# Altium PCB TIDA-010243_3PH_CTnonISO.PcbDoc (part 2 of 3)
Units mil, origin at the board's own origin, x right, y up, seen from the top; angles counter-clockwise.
Board outline 6131.89 x 7490.17 mil, 2 copper layers (Top Layer, Bottom Layer), stack 62 mil thick; 208 components, 218 nets, 747 pads, 147 vias.
Unrouted connection lines stored in the file: 258.
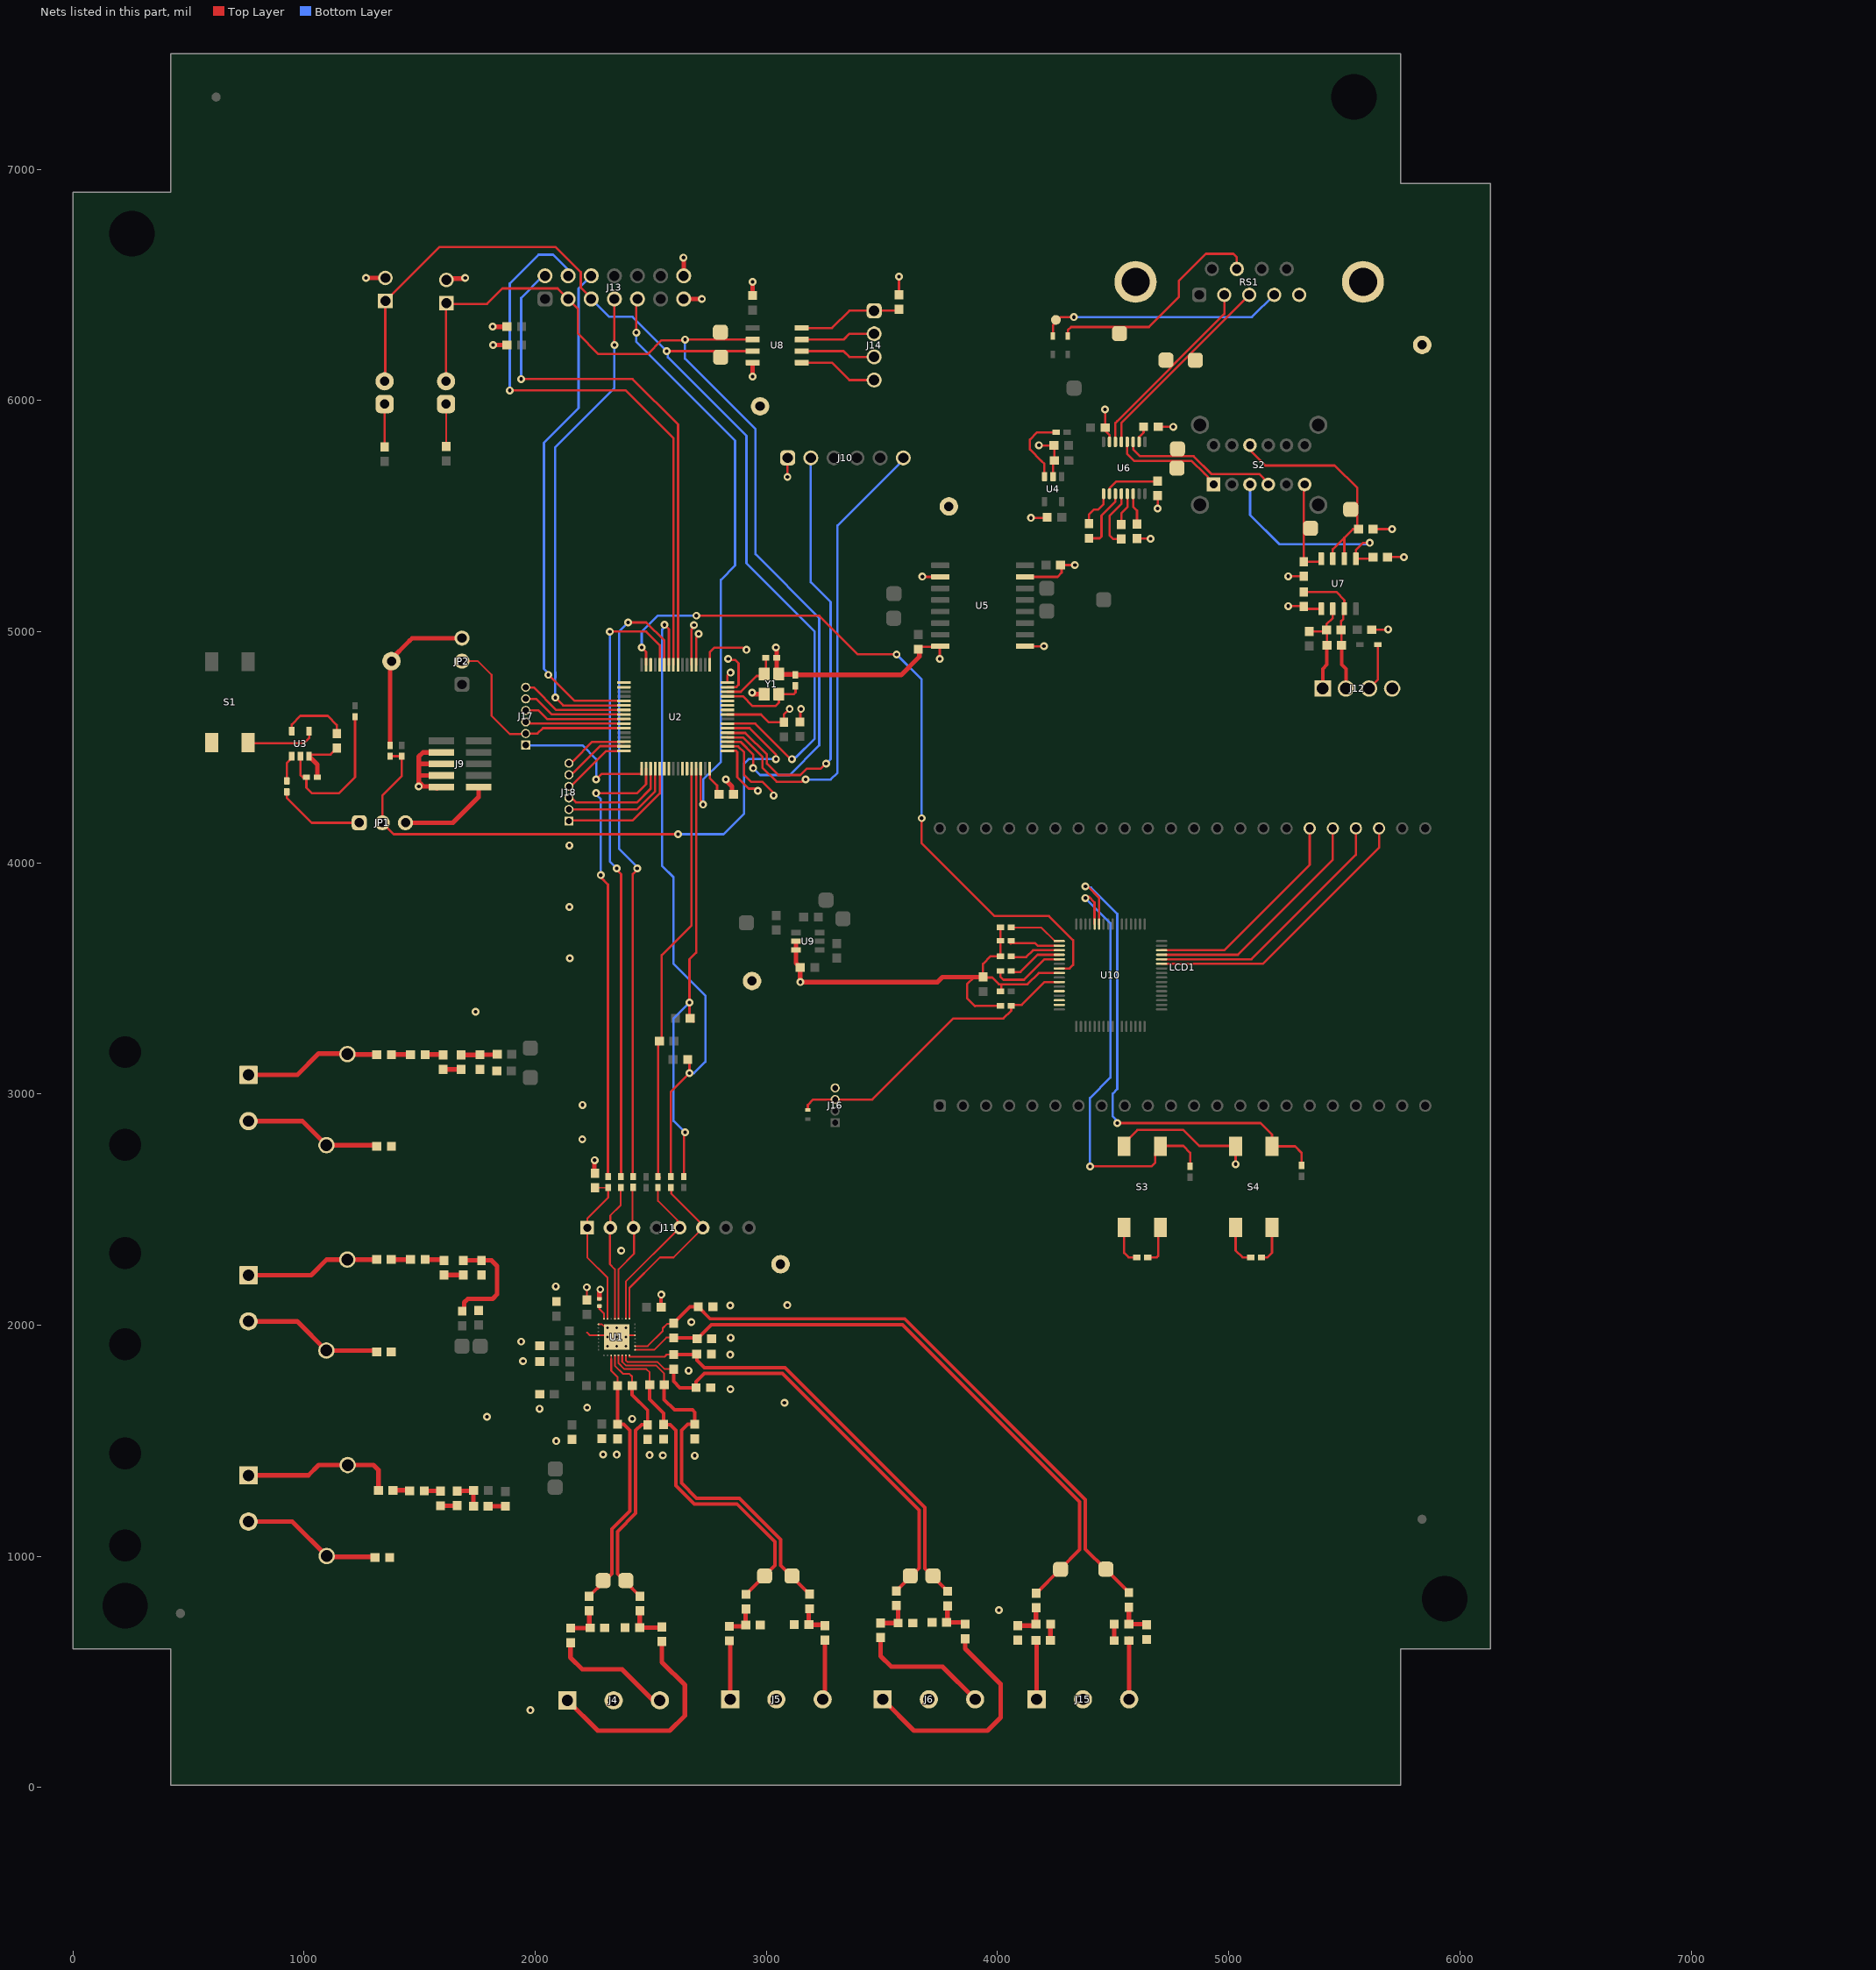
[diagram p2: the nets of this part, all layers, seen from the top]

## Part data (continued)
LBL1: library part CMP-0003625-1, "Thermal Transfer Printable Labels, 0.650\" W x 0.200\" H - 10,000 per roll", Manufacturer=Brady, Supplier Part Number 1=97C5133
LCD1: library part CMP-0079272-1, "160 Segment LCD Display, TH", Manufacturer="Adkom Elektronik"
Logo2: library part CMP-0074844-1
Logo3: library part CMP-0074847-1, "FCC_disclaimer"
logo4: library part CMP-0074835-1, "IEC 61010-1 High Voltage Warning"
Logo4: library part CMP-0074769-1
logo5: library part CMP-0074837-2, "IEC 61010-1 Hot Surface Warning", Manufacturer="Texas Instruments"
R1 R9 R10 R21 R24 R34 R35 R39 R41 R45 R47 R51 R56 R64 R112 R114: library part CMP-0025874-4, "RES, 0, 5%, 0.1 W, AEC-Q200 Grade 0, 0603", Manufacturer=Panasonic, Power_W=100mW, Supplier Part Number 1=P0.0GCT-ND, TempCo="600 ppm/C", Tolerance_%=5%, Value2=0.1W, Value_Code=0000, ValueDisplayed=0
R2 R3 R4 R11 R12 R13 R25 R26 R27: library part CMP-0023521-3, "RES, 330 k, 0.1%, 0.1 W, 0603", Manufacturer="Susumu Co Ltd", Power_W=100mW, Supplier Part Number 1=RG16P330KBCT-ND, TempCo="25 ppm/C", Tolerance_%=0.1%, Value2=0.1W, Value_Code=330k
R5 R8 R14 R19 R28 R33: library part CMP-0084355-1, "RES, 1.00 k, 0.5%, 0.1 W, 0603", Manufacturer=Yageo, Power_W=100mW, TempCo="25 ppm/C", Tolerance_%=0.5%, Value2=0.1W, Value_Code=1k00, ValueDisplayed=1.00k
R6 R16 R31: library part CMP-0001856-2, "Varistor 275 VAC, 100 A, TH", Manufacturer=TDK, Supplier Part Number 1=96K7679
R7 R17 R32: library part CMP-0025554-3, "RES, 750, 0.5%, 0.1 W, 0603", Manufacturer="Yageo America", Power_W=100mW, TempCo="50 ppm/C", Tolerance_%=0.5%, Value2=0.1W, Value_Code=750R, ValueDisplayed=750
R15: library part CMP-0026908-3, "RES, 33, 5%, 0.063 W, AEC-Q200 Grade 0, 0402", Manufacturer=Vishay-Dale, Power_W=63mW, Supplier Part Number 1=541-33JCT-ND, TempCo="200 ppm/C", Tolerance_%=5%, Value2=0.063W, Value_Code=33R0, ValueDisplayed=33
R18 R20 R22 R23 R30: library part CMP-0026908-2, "RES, 33, 5%, 0.063 W, 0402", Manufacturer=Vishay-Dale, Power_W=63mW, Supplier Part Number 1=541-33JCT-ND, TempCo="200 ppm/C", Tolerance_%=5%, Value2=0.063W, Value_Code=33R0, ValueDisplayed=33
R29: library part CMP-0026822-3, "RES, 0, 5%, 0.063 W, AEC-Q200 Grade 0, 0402", Manufacturer=Vishay-Dale, Power_W=63mW, Supplier Part Number 1=541-0.0JCT-ND, TempCo="200 ppm/C", Tolerance_%=5%, Value2=0.063W, Value_Code=0000, ValueDisplayed=0
R36 R40 R42 R46 R48 R52 R109 R110 R111 R113 R115: library part CMP-0025080-3, "RES, 2.00 k, 0.5%, 0.1 W, 0603", Manufacturer="Yageo America", Power_W=100mW, TempCo="25 ppm/C", Tolerance_%=0.5%, Value2=0.1W, Value_Code=2k00, ValueDisplayed=2.00k
R37 R38 R43 R44 R49 R50 R57 R63: library part CMP-0022575-4, "RES, 6.49, 1%, 0.1 W, AEC-Q200 Grade 0, 0603", Manufacturer=Vishay-Dale, Power_W=100mW, Supplier Part Number 1=541-6.49HHCT-ND, TempCo="100 ppm/C", Tolerance_%=1%, Value2=0.1W, Value_Code=6R49, ValueDisplayed=6.49
R53 R54: library part CMP-0022736-2, "RES, 100, 1%, 0.1 W, 0603", Manufacturer="Yageo America", Power_W=100mW, Supplier Part Number 1=311-100HRCT-ND, TempCo="200 ppm/C", Tolerance_%=1%, Value2=0.1W, Value_Code=100R, ValueDisplayed=100
R55 R65: library part CMP-0026935-3, "RES, 47 k, 5%, 0.063 W, AEC-Q200 Grade 0, 0402", Manufacturer=Vishay-Dale, Power_W=63mW, Supplier Part Number 1=541-47KJCT-ND, TempCo="200 ppm/C", Tolerance_%=5%, Value2=0.063W, Value_Code=47k0, ValueDisplayed=47k
R58: library part CMP-0021998-2, "RES, 10.0 k, 1%, 0.1 W, 0603", Manufacturer=Vishay-Dale, Power_W=100mW, Supplier Part Number 1=541-10.0KHCT-ND, TempCo="100 ppm/C", Tolerance_%=1%, Value2=0.1W, Value_Code=10k0, ValueDisplayed=10.0k
R59 R61: library part CMP-0021990-4, "RES, 100 k, 1%, 0.1 W, AEC-Q200 Grade 0, 0603", Manufacturer=Vishay-Dale, Power_W=100mW, Supplier Part Number 1=541-100KHCT-ND, TempCo="100 ppm/C", Tolerance_%=1%, Value2=0.1W, Value_Code=100k
R60 R62: library part CMP-0094948-1, "0 Ohms Jumper 0.1W, 1/10W Chip Resistor 0402 (1005 Metric) - Thick Film", Digikey Part Number=2679-CR0402-10W-000TTR-ND, Manufacturer=Venkel, Operating Temperature Range="-55°C to +155°C", Power_W=100mW
R66 R67: library part CMP-0025950-3, "RES, 100 k, 1%, 0.063 W, AEC-Q200 Grade 0, 0402", Manufacturer=Vishay-Dale, Power_W=63mW, Supplier Part Number 1=541-100KLCT-ND, TempCo="100 ppm/C", Tolerance_%=1%, Value2=0.063W, Value_Code=100k
R101: library part CMP-0027004-2, "RES, 0, 5%, 0.063 W, 0402", Manufacturer="Yageo America", Power_W=63mW, Supplier Part Number 1=311-0.0JRCT-ND, TempCo="200 ppm/C", Tolerance_%=5%, Value2=0.063W, Value_Code=0000, ValueDisplayed=0
R102 R105 R106: library part CMP-0025817-4, "RES, 4.7 k, 5%, 0.1 W, AEC-Q200 Grade 0, 0603", Manufacturer=Vishay-Dale, Power_W=100mW, Supplier Part Number 1=541-4.7KGCT-ND, TempCo="200 ppm/C", Tolerance_%=5%, Value2=0.1W, Value_Code=4k70, ValueDisplayed=4.7k
R103 R108: library part CMP-0025698-4, "RES, 100 k, 5%, 0.1 W, AEC-Q200 Grade 0, 0603", Manufacturer=Vishay-Dale, Power_W=100mW, Supplier Part Number 1=541-100KGCT-ND, TempCo="200 ppm/C", Tolerance_%=5%, Value2=0.1W, Value_Code=100k
R107: library part CMP-0024624-2, "RES, 120, 0.5%, 0.1 W, 0603", Manufacturer="Yageo America", Power_W=100mW, TempCo="50 ppm/C", Tolerance_%=0.5%, Value2=0.1W, Value_Code=120R, ValueDisplayed=120
RS1: library part CMP-0079577-1, "Receptacle, D-SUB-9, 2.74mm, Gold, TH", Color=Black, Current_A=6A, Manufacturer="TE Connectivity", Supplier Part Number 1=A32036-ND, Voltage_V=125V
S1 S3 S4: library part CMP-0002197-2, "Switch, Tactile, SPST-NO, 12 V, SMD", CurrentRating_mA=50A, Manufacturer=APEM, Supplier Part Number 1=679-2461-1-ND
S2: library part CMP-0002195-2, "Switch, Slide, 4PDT,TH", CurrentRating_mA=300A, Manufacturer="TE Connectivity", Supplier Part Number 1=450-1592-ND
TP1 TP2 TP3 TP4 TP5 TP6: library part CMP-0055137-1, "Test Point, Miniature, Red, TH", Color=Red, Manufacturer=Keystone, Supplier Part Number 1=36-5000-ND
U1: library part CMP-0089590-1, "8-Channel, Simultaneously-Sampling, 24-Bit, Delta-Sigma ADC", Manufacturer="Texas Instruments", Max Supply Voltage=3.6V, Min Supply Voltage=1.65V, Operating Temperature Range="-40°C to +125°C"
U2: library part CMP-0093955-1, "Mixed-Signal Microcontrollers LQFP64 80MHz 128KB Flash and 32KB RAM 60 GPIO's 32bits ARM Cortex-M0+ 7 Timers", Frequency_Fixed=80MHz, Manufacturer="Texas Instruments", Max Supply Voltage=3.6V, Min Supply Voltage=1.62V, Operating Temperature Range="-40°C to +125°C"
U3: library part CMP-0084477-1, "Nano Power, Wide VIN Voltage Detector with Programmable Delay, DBV0005A (SOT-23-5)", Alternate Manufacturer="Texas Instruments"
U4: library part CMP-0073793-1, "150-mA, 30-V, Ultra-Low IQ, Wide Input Low-Dropout Regulator with Reverse Current Protection, DBV0005A (SOT-23-5)", Alternate Manufacturer="Texas Instruments", Alternate PartNumber=TPS70933DBVT
U5: library part CMP-0094636-1, Digikey Part Number=296-ISO6731DWRCT-ND, Manufacturer="Texas Instruments", Max Supply Voltage=5.5V, Min Supply Voltage=1.71V, Mouser Part Number=595-ISO6731DWR, Operating Temperature Range="-40°C to +125°C"
U6: library part CMP-0044123-1, "3-V to 5.5-V Multichannel RS-232 Line Driver / Receiver with ±15-kV IEC ESD Protection, 0 to 70 degC, 16-Pin TSSOP (PW), Green (RoHS & no Sb/Br)", Drivers Per Package=2, Supply Voltage(s)(V)="3.3 or 5.0"
U7: library part CMP-0089978-1, "500 kbps RS-485 Transceivers With ±8-kV IEC ESD Protection", Manufacturer="Texas Instruments", Max Supply Voltage=5.5V, Min Supply Voltage=4.5V, Nominal Supply Current=275-440uA, Operating Temperature Range="-40°C to +125°C"
U8: library part CMP-0095064-1, Digikey Part Number=296-ISO6720BDRCT-ND, Manufacturer="Texas Instruments", Max Supply Voltage=5.5V, Min Supply Voltage=1.71V, Mouser Part Number=595-ISO6720BDR, Operating Temperature Range="-40°C to +125°C"
U9: library part CMP-0092928-2, "3-Axis Linear Hall Effect Sensor With I2C Interface SOT23-6", Manufacturer="Texas Instruments", Max Supply Voltage=3.6V, Min Supply Voltage=1.7V, Operating Supply Current=2.3-2.7mA, Operating Temperature Range="-40°C to +125°C"
U10: library part CMP-0076610-2, "16 MHz Ultra-Low-Power Microcontroller with 16 KB FRAM, 2 KB SRAM, 60 IO, 10 ch ADC10, LCD, IR Logic, PM0064A (LQFP-64)", Alternate Manufacturer="Texas Instruments", Alternate PartNumber=MSP430FR4133IPM
Y1: library part CMP-0085525-1, "Crystal, 16.384 MHz, 50 ppm, 10 pF, SMD", Frequency Stability="30 ppm", Frequency Tolerance="50 ppm", Frequency_Fixed=16.384MHz, Load Capacitance="10 pF", Manufacturer=Epson

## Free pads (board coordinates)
  rrect50% 64.96x64.96 smd: 1(1978.35,3070.87) 1(2086.61,1377.95) 1(2293.31,895.67) 1(2391.73,895.67) 1(2800.83,6295.02) 1(2913.39,3740.16) 1(3110.24,915.35) 1(3257.87,3838.58) 1(3331.38,3758.29) 1(3551.63,5164.02) 1(4212.6,5088.58) 1(4330.71,6053.15) 1(4778.18,5790.08) 1(5527.49,5528.23) 2(1978.35,3198.82) 2(2086.05,1299.52) 2(2802.04,6187.02) 2(2992.13,915.35) 2(3550.51,5057.79) 2(4212.6,5187.01) 2(4527.56,6289.37) 2(4728.72,6174.24) 2(4776.02,5707) 2(5353.34,5446.73) 3(1683.07,1909.45) 3(3622.05,915.35) 3(4458.66,5137.8) 3(4855.23,6173.59) 4(1761.81,1909.45) 4(3720.47,915.35) 5(4468.5,944.88) 6(4272.26,943.9)
  round 42.13 smd: 1(4251.97,6348.43)

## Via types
v1: diameter 34, hole 16, Top Layer to Bottom Layer, 97 vias
v2: diameter 34, hole 16, Top Layer to Bottom Layer, tented both sides, 41 vias
v3: diameter 23.62, hole 11.81, Top Layer to Bottom Layer, 9 vias

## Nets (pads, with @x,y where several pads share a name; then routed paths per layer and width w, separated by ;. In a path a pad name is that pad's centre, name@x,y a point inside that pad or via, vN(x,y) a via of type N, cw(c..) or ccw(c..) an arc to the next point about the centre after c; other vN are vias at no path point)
232_DIN: pad.1@4778.18,5790.08 S2.4 U6.11 | length 683.2
  Top Layer w10: U6.11@4586.27,5820.73 4586.27,5787.99 4615.53,5758.72 4847.37,5758.72 4924.36,5681.73 5131.37,5681.73 5170.74,5642.36 S2.4@5170.74,5636.67
232_ROUT: pad.2@4776.02,5707 S2.1 U6.12 | length 484.5
  Top Layer w10: U6.12@4560.68,5820.73 4560.68,5768.4 4591.09,5737.98 4839.68,5737.98 4894.08,5683.58 4925.5,5652.16 4925.5,5645.69 S2.1@4934.52,5636.67
485_D: pad.2@5353.34,5446.73 R105.1 S2.6 U7.4 | length 408.9
  Top Layer w10: S2.6@5324.8,5629.92 5324.32,5629.44 R105.1@5324.32,5302.22 5387.25,5302.22 U7.4@5399.99,5314.97
485_R: C40.2 S2.3 U7.1 | length 905.5
  Top Layer w10: v1@5601.58,5392.51 v1(5610.24,5383.86) 5580.71,5383.86 5549.99,5353.14 U7.1@5549.99,5314.97 5616.18,5314.97 C40.2@5623.76,5322.55
  Bottom Layer w10: S2.3@5092,5636.67 5092,5504.59 5218.6,5377.99 5604.37,5377.99 v1(5610.24,5383.86)
485_RE_DE: pad.1@5527.49,5528.23 R106.1 S2.10 U7.2 U7.3 | length 1109.8
  Top Layer w10: S2.10@5092,5805.97 5092,5784.27 5157.76,5718.5 5458.32,5718.5 5555.99,5620.83 ; U7.3@5449.99,5314.97 5449.99,5356.28 5499.99,5406.28 ; U7.2@5499.99,5314.97 5499.99,5406.28 ; R106.1@5551.17,5433.68 5555.99,5438.5 R106.1@5555.99,5443.32 ; pad.1@5555.99,5528.23 5555.99,5620.83 ; 5499.99,5406.28 5537.03,5443.32 R106.1@5555.99,5443.32 ; R106.1@5555.99,5443.32 5555.99,5620.83
ACLK: U10.15
ACT: D1.2 J7.1 J13.3 pad.1@2800.83,6295.02 U2.35 U8.2 | length 4432.3
  Top Layer w10: D1.2@1614.17,6082.68 1614.17,6417.32 1791.34,6417.32 1858.29,6484.27 2096.87,6484.27 J13.3@2142.23,6438.92 2185.04,6396.11 2185.04,6289.37 2273.62,6200.79 2487.61,6200.79 2546.67,6259.84 v1@2647.64,6259.84 ; v1(2647.64,6263.18) U8.2@2940.24,6263.18 ; U2.35@2831.79,4523.4 2888.02,4523.4 2942.91,4468.5 v1(2942.91,4409.45)
  Bottom Layer w10: v1(2647.64,6263.18) 2647.64,6181.1 2952.76,5875.98 2952.76,5334.65 3228.35,5059.06 3228.35,4507.87 3100.39,4379.92 2972.44,4379.92 v1(2942.91,4409.45)
ACT_ISO: J14.2 U8.7 | length 323.6
  Top Layer w10: U8.7@3152.84,6263.18 3333.58,6263.18 3358.58,6288.18 J14.2@3466.1,6288.18
ADS_CS: R29.2 R59.1 U2.58 | length 2788.4
  Top Layer w10: v1@2568.9,5019.68 2577.86,5010.73 U2.58@2577.86,4856.08 ; R29.2@2586.46,2642.86 2586.46,3009.69 v2(2667.32,3090.55) 2667.32,3149.61 R59.1@2657.48,3159.45
  Bottom Layer w10: v1@2568.9,5029.53 2565.55,5029.53 2554.46,5018.44 2554.46,5015.09 2548.87,5009.5 2548.87,4183.42 2549.21,4183.07 2549.21,3986.22 2598.43,3937.01 2598.43,3562.99 2736.22,3425.2 2736.22,3139.76 2687.01,3090.55 v2(2667.32,3090.55)
  other v1: 2559.06,5029.53
ADS_DIN_MSP_DOUT: R18.2 U2.60 | length 2703.2
  Top Layer w10: v1(2322.83,5000) 2480.32,5000 2538.49,4941.83 U2.60@2538.49,4856.08 ; v1(2352.36,3976.38) 2352.36,3969.88 2371.22,3951.03 2371.22,2643.51 R18.2@2370.39,2642.68
  Bottom Layer w10: v1(2322.83,5000) 2322.83,4005.91 v1(2352.36,3976.38)
ADS_DOUT_MSP_DIN: R20.2 U2.59 | length 2747.8
  Top Layer w10: v1(2401.57,5039.37) 2480.31,5039.37 2558.17,4961.51 U2.59@2558.17,4856.08 ; R20.2@2423.15,2642.86 2422.25,2643.76 2422.25,3951.19 2440.94,3969.88 v1(2440.94,3976.38)
  Bottom Layer w10: v1(2401.57,5039.37) 2362.2,5000 2362.2,4061 2440.94,3982.26 v1(2440.94,3976.38)
ADS_DRDY: R23.2 R58.2 U2.28 | length 1833.2
  Top Layer w10: R23.2@2530.9,2642.86 2530.9,3208.79 2532.56,3210.45 2532.56,3214.65 2546.26,3228.35 R58.2@2547.24,3228.35 ; R23.2@2530.9,2646.26 R23.2@2539.37,2637.8 ; R58.2@2547.24,3232.28 2547.24,3600.39 2676.28,3729.43 U2.28@2676.28,4407.26
ADS_SYNC_RESET: R30.2 R61.1 U2.29 | length 1888.1
  Top Layer w10: R30.2@2642.94,2642.86 2642.94,2678.25 ; 2642.94,2705.54 2642.94,2816.79 2643.05,2816.89 2643.05,2830.05 v2(2647.64,2834.65) ; 2643.06,2679.98 2643.06,2703.72 ; R61.1@2667.32,3336.61 v2(2667.32,3395.67) 2667.32,3582.68 2695.97,3611.32 U2.29@2695.97,4407.26 ; R61.1@2680.12,3316.93 R61.1@2683.98,3313.07
  Bottom Layer w10: v2(2647.64,2834.65) 2598.43,2883.86 2598.43,3326.77 v2(2667.32,3395.67)
BTN1: R67.1 S4.4 U10.59 | length 2240.4
  Top Layer w10: v1(4379.92,3897.64) 4389.76,3897.64 4438.98,3848.42 U10.59@4438.98,3735.24 ; v1(4517.72,2874.02) 5137.8,2874.02 5187.01,2824.8 S4.4@5187.01,2773.62 5287.4,2773.62 5314.96,2746.06 R67.1@5314.96,2690.94 R67.1@5314.96,2687.01
  Bottom Layer w10: v1(4379.92,3897.64) 4384.51,3893.05 4404.2,3893.05 4517.72,3779.53 4517.72,3021.65 4498.03,3001.97 4498.03,2903.54 4510.01,2891.56 4510.01,2888.22 4517.72,2880.51 v1(4517.72,2874.02)
BTN2: R66.1 S3.4 U10.60 | length 1935.9
  Top Layer w10: v1@4394.06,3853.62 4419.29,3828.39 U10.60@4419.29,3735.24 ; v1(4399.61,2687.01) 4665.35,2687.01 4682.17,2703.82 4682.17,2743.19 4714.57,2775.59 4803.15,2775.59 4832.68,2746.06 R66.1@4832.68,2687.01
  Bottom Layer w10: v1@4379.92,3848.43 v1(4379.92,3847.76) 4488.19,3739.5 4488.19,3070.87 4399.61,2982.28 v1(4399.61,2687.01)
CLKIN_ADS_T: C45.1 J11.1 R15.1 U1.23 | length 695.1
  Top Layer w6: C45.1@2258.61,2594.04 2308.61,2594.04 R15.1@2306.69,2592.12 ; R15.1@2312.84,2598.27 R15.1@2312.99,2598.43
  Top Layer w8: U1.23@2312.99,2027.56 2312.99,2204.72 2224.8,2292.91 J11.1@2224.8,2421.26 2224.8,2461.02 2306.69,2542.91 2315.5,2551.72 R15.1@2315.5,2595.61
COM0: LCD1.28 U10.46 | length 937.4
  Top Layer w10: U10.46@4709.65,3622.05 4980.31,3622.05 5350,3991.73 5350,4129.53 LCD1.28@5354.33,4133.86
COM1: LCD1.27 U10.45 | length 1008.9
  Top Layer w10: U10.45@4729.25,3602.36 5039.37,3602.36 5450,4012.99 LCD1.27@5450,4131.1
COM2: LCD1.26 U10.44 | length 1142.4
  Top Layer w10: U10.44@4709.65,3582.68 5098.43,3582.68 5550,4034.25 LCD1.26@5550,4149.21
COM3: LCD1.25 U10.43 | length 1232.3
  Top Layer w10: U10.43@4709.65,3562.99 5147.64,3562.99 5650,4065.35 LCD1.25@5650,4149.21
CS_ADS_T: J11.6 R29.1 U1.17 | length 792.9
  Top Layer w8: U1.17@2407.48,2027.97 2407.48,2161.42 2539.37,2293.31 2598.43,2293.31 2724.8,2419.69 2724.8,2432.68 2588.58,2568.9 R29.1@2588.58,2598.43
CTS_FTDI: J10.2 U2.37 | length 1911.2
  Top Layer w10: U2.37@2831.79,4562.77 2832.7,4561.86 2859.92,4561.86 2908.61,4561.86 3001.97,4468.5 3001.97,4429.13 3051.18,4379.92 3146.73,4379.92 3173.96,4407.15 3234.6,4407.15 3256.58,4429.13 v1(3257.87,4429.13)
  Bottom Layer w10: J10.2@3191.88,5751.41 3191.88,5213.63 3277.56,5127.95 3277.56,4448.82 v1(3257.87,4429.13)
DIN_ADS_T: J11.2 R18.1 U1.21 | length 593.2
  Top Layer w8: J11.2@2322.83,2411.42 2322.83,2263.78 2344.49,2242.13 U1.21@2344.49,2027.56 ; J11.2@2322.83,2431.1 2324.8,2433.07 2324.8,2474.52 2369.97,2519.69 R18.1@2369.97,2601.1 ; J11.2@2323.18,2411.07 2324.8,2412.7 J11.2@2324.8,2421.26
DOUT_ADS_T: J11.3 R20.1 U1.20 | length 597.6
  Top Layer w8: U1.20@2360.24,2027.97 2360.24,2242.13 2427.17,2309.06 J11.3@2427.17,2421.26 ; R20.1@2421.26,2594.87 2421.26,2424.8 J11.3@2424.8,2421.26 ; R20.1@2423.24,2595.97 R20.1@2424.33,2594.87
DRDY_ADS_T: J11.5 R23.1 U1.18 | length 707
  Top Layer w8: U1.18@2391.73,2027.97 2391.73,2188.19 J11.5@2624.8,2421.26 2615.03,2431.03 2615.03,2453.86 2531.27,2537.63 2531.27,2592.35 2532.64,2590.98 2532.64,2593.87 R23.1@2530.9,2595.61
DVDD_ISO_Pulse: C44.1 J14.1 U8.8 | length 454.3
  Top Layer w10: U8.8@3152.84,6313.18 3283.58,6313.18 3358.58,6388.18 J14.1@3466.1,6388.18 3567.4,6388.18 C44.1@3573.51,6394.29
EM_RX_SECC_TX_UART: J13.4 U2.57 | length 2594.6
  Top Layer w10: v2(1889.76,6043.31) 2391.73,6043.31 2597.54,5837.5 U2.57@2597.54,4856.08
  Bottom Layer w10: v2(1889.76,6043.31) 1889.76,6505.91 2014.21,6630.36 2077.54,6630.36 2142.23,6565.67 J13.4@2142.23,6538.92
EM_SECC_GPIO_UART: J13.6 U2.5 | length 2191.4
  Top Layer w10: v1(2057.09,4812.99) 2169.51,4700.57 U2.5@2382.97,4700.57
  Bottom Layer w10: v1(2057.09,4812.99) 2057.09,4818.88 2037.4,4838.56 2037.4,5816.93 2187.58,5967.11 2187.58,6484.27 J13.6@2242.23,6538.92
EM_TX_SECC_RX_UART: J13.2 U2.56 | length 2294.1
  Top Layer w10: v2(1938.98,6092.52) 2421.26,6092.52 2618.04,5895.74 2618.04,4856.89 U2.56@2617.23,4856.08
  Bottom Layer w10: v2(1938.98,6092.52) 1938.98,6443.19 2034.71,6538.92 J13.2@2042.23,6538.92
GND: C1.2 C3.1 C4.2 C5.2 C6.2 C7.2 C9.1 C10.2 C12.1 C13.2 C15.1 C16.2 C18.1 C19.2 C21.1 C22.1 C23.1 C24.2 C25.1 C26.1 C27.2 C28.2 C31.2 C41.2 C42.1 C43.2 C45.2 C46.2 C47.2 C49.1 C51.2 C52.1 C53.1 C54.1 C56.2 C57.2 C58.2 J4.2 J5.2 J6.2 J7.2 J8.2 J9.3 J9.5 J9.7 J9.9 J10.1 J13.13 J13.14 J15.2 J16.4 JP2.3 R7.1 R8.1 R9.2 R17.1 R19.1 R21.2 R32.1 R33.1 R34.2 R37.1 R38.2 R43.1 R44.2 R49.1 R50.2 R57.1 R63.2 S1.1 S3.2 S4.2 TP1.1 TP2.1 TP3.1 TP4.1 TP6.1 U1.13 U1.25 U1.28 U1.33 U2.41 U3.3 U5.2 U5.8 U8.4 U9.2 U9.3 U10.8 Y1.2 Y1.4 | length 6981.9
  Top Layer w6: U1.28@2273.21,1956.69 2305.12,1956.69 v3(2312.99,1948.82) ; U1.25@2273.21,2003.94 2289.35,2003.94 2291.76,2001.53 ; 2291.81,2001.53 U1.33@2298.77,1994.56 ; U1.33@2298.77,1994.51 2305.09,1988.19 v3(2312.99,1988.19) ; v3(2391.73,1948.82) U1.33@2399.61,1956.69
  Top Layer w8: C6.2@2222.82,2109.26 v1(2222.82,2164.25) ; 2224.41,1968.5 2236.22,1956.69 U1.28@2273.21,1956.69 ; U1.33@2399.61,1956.69 U1.13@2431.1,1956.69
  Top Layer w10: U3.3@1028.46,4468.5 1115.16,4468.5 1141.73,4495.08 C25.1@1141.73,4498.03 ; U2.41@2831.79,4641.51 2914.82,4641.51 2976.6,4641.51 3010.25,4607.86 C51.2@3075.57,4607.86 3075.57,4640.53 v1(3100.39,4665.35) ; v1(3090.94,5669.29) 3090.94,5750.47 J10.1@3091.88,5751.41 ; C23.1@3141.33,4607.86 C23.1@3146.97,4613.5 ; C23.1@3149.61,4616.14 C23.1@3146.97,4613.5 ; v1(3149.61,4665.35) 3146.97,4662.72 C23.1@3146.97,4613.5 ; C31.2@3658,4924.68 3667.06,4933.75 3748.92,4933.75 U5.8@3750,4934.82 ; v1(3674.61,5237.88) 3675.6,5236.9 U5.2@3752.07,5236.9 ; v2(3750,4881.89) U5.8@3750,4934.82 ; U5.8@3752.07,4936.9 U5.8@3750,4934.82 ; 3899.61,3505.91 3868.11,3474.41 3868.11,3413.8 3901.78,3380.13 3902.68,3381.03 C58.2@4011.81,3381.03 ; C56.2@3937.01,3513.78 3937.01,3562.99 3970.02,3596 4001.06,3596 4005.91,3600.84 C52.1@4005.91,3602.36 ; C56.2@3946.85,3503.94 3976.38,3503.94 4005.91,3474.41 4015.75,3474.41 ; C57.2@4011.81,3444 4015.75,3447.94 4015.75,3474.41 ; C52.1@4011.81,3602.36 C53.1@4011.81,3653.07 ; C53.1@4011.81,3655.51 C54.1@4011.81,3721.08 ; U10.8@4266.73,3523.62 4178.15,3523.62 4128.94,3474.41 4015.75,3474.41 ; S3.2@4547.24,2773.62 4547.24,2787.4 4604.33,2844.49 4803.15,2844.49 4872.05,2775.59 S4.2@5029.53,2775.59 ; v2(5029.53,2696.85) S4.2@5029.53,2773.62
  Top Layer w15: C5.2@2544.44,2077.77 2544.44,2131.46 v1(2545.09,2132.11)
  Top Layer w20: U3.3@1023.62,4458.66 1057.09,4425.2 C26.1@1057.09,4370.08 ; v1(1267.96,6529.86) J8.2@1351.46,6529.86 ; C24.2@1372.05,4508.27 1372.05,4875.98 1456.69,4960.63 ; 1466.54,4970.47 1467.32,4971.26 1682.28,4971.26 JP2.3@1683.07,4970.47 ; v2(1496.06,4330.71) v2@1505.91,4340.55 ; J9.9@1574.8,4320.87 1564.96,4330.71 1515.75,4330.71 v2@1505.91,4340.55 ; J9.7@1594.49,4377.56 1498.43,4377.56 1496.06,4379.92 ; J9.5@1594.49,4427.56 1497.64,4427.56 1496.06,4429.13 ; J9.3@1594.49,4477.56 1514.96,4477.56 1496.06,4458.66 1496.06,4429.13 ; J7.2@1615.88,6521.1 1621.97,6527.18 1694.4,6527.18 v1(1697.07,6529.86) ; R32.1@1795.78,1216.8 1869.71,1216.8 R33.1@1870.12,1217.21 ; v1(1815.64,6318.9) C42.1@1877.95,6318.9 ; v1(1817.18,6240.16) C41.2@1877.95,6240.16 ; R8.1@1826.72,3106.12 R8.1@1833.52,3099.32 ; C9.1@2019.52,1840.23 C9.1@2019.52,1842.22 ; v1(2089.34,2167.74) v1@2091.78,2165.3 ; v1(2256.95,2713.65) 2255.82,2712.52 2255.82,2659.82 C45.2@2258.61,2657.03 ; C4.2@2277.32,2114.26 2277.32,2150.75 v1(2281.29,2154.72) ; R37.1@2387.44,691.19 R37.1@2388.6,692.35 ; C13.2@2485.99,1506.31 2485.99,1505.32 C13.2@2488.49,1502.82 ; v1(2641.33,6617.71) 2642.23,6616.81 J13.14@2642.23,6538.92 ; J13.13@2642.23,6438.92 v1(2720.93,6438.92) ; v1(2824.8,4360.24) 2824.8,4356.45 2850.96,4330.29 2850.96,4303.08 C22.1@2857.76,4296.28 ; v1(2938.6,4735.92) 2938.6,4729.5 Y1.2@2990.67,4729.5 ; v1(2940.24,6102.81) U8.4@2940.24,6163.18 ; C43.2@2940.24,6454.1 v1(2940.24,6513.22) ; v2(3041.34,4931.1) 3044.62,4927.82 C27.2@3044.62,4886.51 3044.62,4825.16 Y1.4@3057.09,4812.69 ; Y1.4@3053.66,4816.12 Y1.4@3057.09,4812.69 ; R44.2@3119.4,703.96 R44.2@3120.12,704.69 ; C28.2@3122.98,4814.36 3058.76,4814.36 Y1.4@3057.09,4812.69 ; C28.2@3124.74,4812.6 3582.28,4812.6 3661.42,4891.73 C31.2@3661.42,4921.26 ; U9.2@3127.95,3660.89 U9.3@3127.95,3623.48 3127.95,3566.05 C46.2@3146.29,3547.71 v1(3146.29,3484.25) 3740.16,3484.25 3761.81,3505.91 3899.61,3505.91 3929.13,3505.91 C56.2@3937.01,3513.78 ; R50.2@3632.82,711.59 R50.2@3635.77,714.54 ; R49.1@3713.71,711.59 R49.1@3716.46,714.34 ; 1496.06,4379.92 1496.06,4429.13 ; 1496.06,4379.92 1496.06,4350.39 v2@1505.91,4340.55
  Bottom Layer w25: v3(2312.99,1909.45) v3(2312.99,1948.82) ; v3(2312.99,1988.19) v3(2312.99,1948.82) ; v3(2352.36,1909.45) v3(2352.36,1948.82) ; v3(2352.36,1988.19) v3(2352.36,1948.82) ; v3(2391.73,1909.45) v3(2391.73,1948.82) ; v3(2391.73,1988.19) v3(2391.73,1948.82) ; v3(2312.99,1948.82) v3(2352.36,1948.82) ; v3(2352.36,1948.82) v3(2391.73,1948.82)
  other v1: 1978.35,334.65 4005.91,767.72 2689.64,1435.92 2494.05,1438.16 2552.06,1437.41 2352.11,1440.31 2293.27,1440.39 2090.88,1498.89 2419.31,1595.14 1791.34,1604.33 2018.26,1638.61 2224.41,1643.7 3077.76,1664.67 2844.46,1723.25 2663.49,1803.66 1947.35,1845.14 2843.23,1872.29 1938.98,1929.13 2845.5,1946.08 2675.31,2012.96 2843.94,2085.82 3090.55,2086.61 2372.05,2322.83 2203.49,2804.02 2204.72,2952.76 1742.13,3356.3 2149.22,3587.46 2147.55,3809.34 2147.78,4075.04
GND_ISO_Pulse: C44.2 J14.4 U8.5 | length 422.9
  Top Layer w10: U8.5@3152.84,6163.18 3283.58,6163.18 3358.58,6088.18 J14.4@3466.1,6088.18 ; C44.2@3573.51,6457.28 v1(3573.51,6535.88)
GND_ISO_RS: C29.1 C30.2 C32.1 C33.1 C34.2 C35.2 C39.2 C40.1 C50.2 J12.4 R102.1 R105.2 R106.2 R108.1 RS1.5 RS1.10 RS1.11 TP5.1 U4.2 U5.9 U5.15 U6.15 U7.5 | length 1394.8
  Top Layer w10: U5.9@4118.21,4936.9 v1(4200.21,4936.9) ; U5.15@4118.21,5236.9 4258.94,5236.9 4277.03,5254.99 C34.2@4277.03,5288.08 ; v1(4143.7,5492.13) 4211.34,5492.13 C50.2@4214.23,5495.02 ; v1(4178.84,5806.4) 4180.11,5805.13 C30.2@4244.4,5805.13 4245.72,5803.81 C35.2@4245.72,5740.02 4239.89,5734.19 U4.2@4239.89,5670.7 ; C34.2@4272.67,5288.08 C34.2@4277.03,5288.08 ; v1(4334.53,5288.08) C34.2@4277.03,5288.08 ; v1(4464.88,5960.94) C29.1@4464.88,5882.58 4464.88,5869.77 4483.9,5850.74 U6.15@4483.9,5820.73 ; C32.1@4603.05,5402.06 v1(4661.34,5402.06) ; v1(4692.56,5532.4) C33.1@4692.56,5588.02 ; R102.1@4694.24,5885.87 v1(4759.5,5885.87) ; v1@5250.83,5116.36 v1(5256.69,5110.5) 5322.54,5110.5 R108.1@5324.56,5108.47 5334.6,5098.43 U7.5@5399.99,5098.43 ; v1(5256.69,5239.23) R105.2@5324.32,5239.23 ; C39.2@5618.79,5008.07 5687.2,5008.07 v1(5688.98,5009.84) ; R106.2@5623.81,5443.32 v1(5706.61,5443.32) ; C40.1@5686.76,5322.55 v1(5757.88,5322.55)
HFXIN: C28.1 U2.45 Y1.3 | length 385.8
  Top Layer w10: U2.45@2831.79,4720.25 2897.86,4720.25 2940.12,4677.99 3039.06,4677.99 3053.66,4692.59 Y1.3@3053.66,4729.5 3117.88,4729.5 3125.96,4737.58 C28.1@3125.96,4763.79 ; C28.1@3124.74,4763.8 C28.1@3124.74,4765.35
HFXOUT: C27.1 U2.46 Y1.1 | length 263.6
  Top Layer w10: U2.46@2831.79,4739.94 2889.54,4739.94 2957.91,4808.3 2982.86,4808.3 2997.38,4822.82 C27.1@2997.38,4886.51
I_Neutral_N: C48.2 C49.2 pad.5 R115.2 U1.10 | length 2852.1
  Top Layer w8: U1.10@2431.51,1909.45 2486.64,1909.45 2551.4,1974.21 2551.4,1986.69 2570.06,2005.35 2595.57,2005.35 C48.2@2598.61,2008.39
  Top Layer w15: C48.2@2598.61,2008.39 2598.61,2009.37 2609.81,2020.57 2610.79,2020.57 2669.51,2079.3 C49.2@2705,2079.3 2756.66,2027.64 3598.27,2027.64 4379.84,1246.06 4379.84,1031.84 4467.65,944.03 R115.2@4568.05,843.64
I_Neutral_P: C47.1 C48.1 pad.6 R113.2 U1.9 | length 2775.3
  Top Layer w6: U1.9@2431.51,1893.7 2443.89,1893.7
  Top Layer w8: U1.9@2431.59,1893.58 2443.89,1893.58 2487.67,1893.58 2514.45,1893.74 2567.09,1946.38 C48.1@2598.61,1946.38 ; C47.1@2696.55,1945.39 C47.1@2700.51,1941.43
  Top Layer w15: C48.1@2598.61,1945.39 2624.7,1945.39 C47.1@2696.55,1945.39 ; C47.1@2700.51,1941.43 2700.51,1941.64 2761.51,2002.64 3587.91,2002.64 4354.84,1235.71 4354.84,1028.83 4271.08,945.07 R113.2@4166.64,840.62
I_Phase_A_N: C14.2 C15.2 pad.1@2293.31,895.67 R40.2 U1.3 | length 1165.3
  Top Layer w6: 2328.74,1854.33 U1.3@2328.74,1869.67
  Top Layer w8: 2328.83,1854.7 2328.83,1803.2 2356,1776.04 C14.2@2356,1738.7 C14.2@2355.56,1738.26
  Top Layer w15: R40.2@2233.37,827.42 2297.46,891.51 2330.79,924.84 2330.79,1118.11 2409.71,1197.03 2409.71,1544.32 2382.53,1571.5 C15.2@2355.56,1571.5 C14.2@2355.56,1738.26
I_Phase_A_P: C13.1 C14.1 pad.1@2391.73,895.67 R36.2 U1.4 | length 1227.1
  Top Layer w8: U1.4@2344.49,1869.67 2344.49,1824.41 2378.79,1790.11 2406.98,1790.11 2418.99,1778.1 C14.1@2418.99,1738.7
  Top Layer w15: C14.1@2418.99,1738.7 2418.99,1698.76 2485.99,1631.75 C13.1@2485.99,1569.3 2459.69,1569.3 2434.71,1544.32 2434.71,1186.68 2355.79,1107.76 2355.79,924.84 2388.35,892.28 R36.2@2453.21,827.42
I_Phase_B_N: C17.2 C18.2 pad.1@3110.24,915.35 R46.2 U1.6 | length 1664.2
  Top Layer w8: U1.6@2375.98,1870.08 2375.98,1842.89 2376.23,1842.64 2376.23,1841.68 2391.81,1826.1 2521.89,1826.1 2557.88,1790.11 C17.2@2557.88,1742.21
  Top Layer w15: C17.2@2557.88,1742.21 2557.88,1678.42 2602.44,1633.86 2679.63,1633.86 2689.65,1623.84 C18.2@2689.65,1571.5 2659.22,1571.5 2632.87,1545.15 2632.87,1317.19 2698.01,1252.05 2883.16,1252.05 3061.86,1073.35 3061.86,961.02 3108.88,914 R46.2@3186.49,836.39
I_Phase_B_P: C16.1 C17.1 pad.2@2992.13,915.35 R42.2 U1.5 | length 1546.3
  Top Layer w8: U1.5@2360.24,1870.08 2360.24,1835.32 2385.44,1810.11 2480.52,1810.11 2494.89,1795.74 C17.1@2494.89,1742.21
  Top Layer w15: C17.1@2494.89,1742.21 2494.89,1679.02 2555.37,1618.53 C16.1@2555.37,1570.13 2582.89,1570.13 2607.87,1545.15 2607.87,1306.83 2687.65,1227.05 2872.8,1227.05 3036.86,1062.99 3036.86,960.6 2991.87,915.61 R42.2@2912.23,835.97
I_Phase_C_N: C20.2 C21.2 pad.3@3622.05,915.35 R52.2 U1.7 | length 2046.1
  Top Layer w8: U1.7@2391.73,1870.08 2391.73,1848.1 2398.23,1841.6 2528.31,1841.6 2559.8,1810.11 C20.2@2598.46,1810.11
  Top Layer w15: C20.2@2598.46,1810.11 2598.46,1757.21 2625.79,1729.88 C21.2@2695.57,1729.88 2695.57,1754.97 2732.01,1791.41 3069.55,1791.41 3660.17,1200.79 3660.17,948.78 3624.39,913.01 R52.2@3561.94,850.55
I_Phase_C_P: C19.1 C20.1 pad.4@3720.47,915.35 R48.2 U1.8 | length 1982.7
  Top Layer w6: 2407.48,1863.26 U1.8@2407.48,1870.08 ; C19.1@2696.59,1873.1 C19.1@2699.12,1875.63
  Top Layer w8: 2407.48,1863.26 2558.91,1863.26 2568.75,1873.1 C20.1@2598.46,1873.1
  Top Layer w15: C20.1@2598.46,1873.1 C19.1@2696.59,1873.1 ; C19.1@2699.12,1875.63 2699.12,1849.29 2732.01,1816.41 3079.9,1816.41 3685.17,1211.14 3685.17,947.66 3718.97,913.85 R48.2@3783.4,849.42
LCDCAP0: C55.2 U10.5 | length 321.4
  Top Layer w10: C55.2@4011.81,3532 4011.81,3507.87 4025.59,3494.09 4114.17,3494.09 4202.76,3582.68 U10.5@4266.73,3582.68
LCDCAP1: C55.1 U10.4 | length 238.5
  Top Layer w10: C55.1@4059.05,3528 4098.87,3528 4173.23,3602.36 U10.4@4266.73,3602.36
LFCLK_OUT: U2.63 U10.7 | length 3215.6
  Top Layer w10: v2(2460.63,4931.1) 2479.43,4912.3 U2.63@2479.43,4856.08 ; v2(2696.85,5068.9) 3228.35,5068.9 3395.67,4901.57 v2(3562.99,4901.57) ; v2(3671.26,4192.91) 3671.26,4084.65 3986.22,3769.68 4222.44,3769.68 4326.57,3665.56 4326.57,3558.85 4311.02,3543.31 U10.7@4266.73,3543.31
  Bottom Layer w10: v2(2460.63,4931.1) 2460.63,5000 2529.53,5068.9 v2(2696.85,5068.9) ; v2(3562.99,4901.57) 3671.26,4793.31 v2(3671.26,4192.91)
M0_CLKOUT: R15.2 U2.18 | length 1982.2
  Top Layer w10: v2(2263.78,4301.18) 2440.94,4301.18 2479.43,4339.67 U2.18@2479.43,4407.26 ; v2(2283.46,3946.85) 2283.46,3937.01 2314.24,3906.23 R15.2@2314.24,2639.05
  Bottom Layer w10: v2(2263.78,4301.18) 2263.78,4295.3 2283.46,4275.61 v2(2283.46,3946.85)
M0_EN_from_SECC: J13.7 U2.6 | length 2176.9
  Top Layer w10: v1@2086.61,4724.41 v1(2086.61,4714.57) 2120.3,4680.88 U2.6@2382.97,4680.88 ; J13.7@2342.23,6438.92 2334.9,6431.59 2341.89,6424.61 2341.89,6240.79 v1(2342.52,6240.16)
  Bottom Layer w10: v1(2086.61,4714.57) 2086.61,4800.27 2086.96,4800.62 2086.96,4825.37 2086.61,4825.71 2086.61,5797.24 2342.52,6053.15 v1(2342.52,6240.16) 2342.52,6259.53 2342.13,6259.92
M0_GPIO1_SECC: J13.9 U2.30 | length 2583.1
  Top Layer w10: v1(2437.04,6293.37) 2437.04,6433.73 J13.9@2442.23,6438.92 ; U2.30@2715.65,4407.26 2715.65,4269.19 2726.38,4258.46 v1(2726.38,4251.97)
  Bottom Layer w10: v1(2437.04,6293.37) 2437.04,6253.91 2864.52,5826.43 2864.52,5285.78 2802.93,5224.19 2802.93,4436.79 2726.38,4360.24 v1(2726.38,4251.97)
Meter_RX_PC_TX: pad.3@4855.23,6173.59 RS1.3 U6.13 | length 865.2
  Top Layer w10: U6.13@4535.09,5820.73 4535.09,5903.15 RS1.3@5088.63,6456.69
Meter_TX_PC_RX: pad.2@4728.72,6174.24 RS1.2 U6.14 | length 831.1
  Top Layer w10: U6.14@4509.49,5820.73 4509.49,5894.13 4509.49,5902.22 4517.59,5910.31 4517.59,5910.4 4980.63,6373.44 RS1.2@4980.63,6456.69
NetC4_1: C4.1 U1.24 | length 63.5
  Top Layer w6: U1.24@2295.74,2029.07 U1.24@2297.24,2027.56
  Top Layer w8: C4.1@2277.32,2082.77 2277.32,2070.27 2295.74,2051.86 ; U1.24@2297.24,2027.56 2297.24,2050.35
NetC22_2: C22.2 U2.32 | length 132.2
  Top Layer w10: U2.32@2755.02,4407.26 2755.02,4366.68 2786.64,4335.06 2786.64,4296.28 C22.2@2794.76,4296.28
NetC25_2: C25.2 U3.5 | length 293
  Top Layer w10: U3.5@946.85,4569.54 946.85,4598.43 984.25,4635.83 1102.36,4635.83 1141.73,4596.46 1141.73,4586.61 C25.2@1141.73,4559.05
NetC26_2: C26.2 R62.2 U3.2 | length 661.2
  Top Layer w10: U3.2@984.25,4461.27 984.25,4379.92 994.09,4370.08 C26.2@1003.94,4370.08 ; C26.2@1009.84,4370.08 1009.84,4324.8 1033.46,4301.18 1151.57,4301.18 1220.47,4370.08 R62.2@1220.47,4631.89
NetC32_2: C32.2 U6.6 | length 138.2
  Top Layer w10: U6.6@4586.27,5596.32 4586.27,5540.31 4603.05,5523.53 C32.2@4603.05,5465.05
NetC33_2: C33.2 U6.2 | length 244.9
  Top Layer w10: U6.2@4483.9,5596.32 4483.9,5619.52 4513.82,5649.43 4632.62,5649.43 4690.98,5649.43 C33.2@4692.56,5651.02
NetC36_1: C36.1 U6.5 | length 145
  Top Layer w10: C36.1@4535.09,5463.35 4535.09,5512.01 4562.35,5539.28 4562.35,5594.64 U6.5@4560.68,5596.32
NetC36_2: C36.2 U6.4 | length 259
  Top Layer w10: C36.2@4535.09,5400.36 4499.88,5400.36 4483.9,5416.33 4483.9,5501.21 4535.09,5552.39 U6.4@4535.09,5596.32
NetC37_1: C37.1 U6.3 | length 266.8
  Top Layer w10: C37.1@4395.39,5403.54 4441.09,5403.54 4449.45,5411.9 4449.45,5502.44 4509.49,5562.48 U6.3@4509.49,5596.32
NetC37_2: C37.2 U6.1 | length 166.2
  Top Layer w10: C37.2@4395.39,5466.53 4395.39,5507.19 4415.65,5527.46 4433.38,5527.46 4458.31,5552.39 U6.1@4458.31,5596.32
NetC59_1: C59.1 S4.3 | length 163.7
  Top Layer w10: C59.1@5141.73,2293.31 5167.32,2293.31 5187.01,2312.99 S4.3@5187.01,2423.23
NetC59_2: C59.2 S4.1 | length 181.5
  Top Layer w10: S4.1@5029.53,2423.23 5029.53,2322.83 5059.06,2293.31 C59.2@5094.49,2293.31 C59.2@5098.43,2293.31
NetC60_1: C60.1 S3.3 | length 179.6
  Top Layer w10: C60.1@4649.61,2293.31 4689.02,2293.31 4694.88,2299.16 S3.3@4694.88,2431.1
NetC60_2: C60.2 S3.1 | length 177.4
  Top Layer w10: S3.1@4547.24,2423.23 4547.24,2312.99 4566.93,2293.31 C60.2@4602.36,2293.31 C60.2@4606.3,2293.31
NetD1_1: D1.1 R53.1 | length 183.1
  Top Layer w8: R53.1@1614.17,5801.18 D1.1@1614.17,5984.25
NetD2_1: D2.1 R54.1 | length 185
  Top Layer w8: R54.1@1348.43,5799.21 D2.1@1348.43,5984.25
NetD5_2: D5.2 J12.3 | length 206.1
  Top Layer w10: J12.3@5606.61,4753.94 5645.36,4792.69 D5.2@5645.36,4944.03
NetJ1_1: J1.1 R1.1 R6.1 | length 595.2
  Top Layer w20: J1.1@759.85,3082.84 970.91,3082.84 1063.23,3175.16 1184.87,3175.16 R6.1@1187.58,3172.45 1189.37,3170.66 R1.1@1314.96,3170.66
NetJ1_2: J1.2 R6.2 R9.1 | length 600.1
  Top Layer w20: J1.2@759.85,2882.84 992.94,2882.84 R6.2@1097.03,2778.75 1310.32,2778.75 R9.1@1314.96,2774.1
NetJ2_1: J2.1 R10.1 R16.1 | length 582.5
  Top Layer w20: J2.1@759.85,2216.74 1030.88,2216.74 1098.16,2284.02 R16.1@1187.01,2284.02 R10.1@1314.43,2284.06 R10.1@1314.43,2284.06
NetJ2_2: J2.2 R16.2 R21.1 | length 609.4
  Top Layer w20: J2.2@759.85,2016.74 970.03,2016.74 R16.2@1096.46,1890.32 1308.55,1890.32 R21.1@1314.43,1884.44
NetJ3_1: J3.1 R24.1 R31.1 | length 677.1
  Top Layer w20: J3.1@759.85,1350.65 1018.53,1350.65 1063.23,1395.34 1188.15,1395.34 R31.1@1188.3,1395.19 1300.4,1395.19 1321.53,1374.06 R24.1@1321.53,1286
NetJ3_2: J3.2 R31.2 R34.1 | length 615.6
  Top Layer w20: J3.2@759.85,1150.65 948.59,1150.65 R31.2@1100.62,998.62 ; R31.2@1097.75,1001.49 R31.2@1100.62,998.62 ; R34.1@1307.21,995.75 1304.34,998.62 R31.2@1100.62,998.62
NetJ4_1: J4.1 R35.1 | length 951.6
  Top Layer w20: J4.1@2139.06,377.39 2270.39,246.06 2581.98,246.06 2647.64,311.72 2647.64,442.91 2547.8,542.75 R35.1@2547.8,631.77
NetJ4_3: J4.3 R39.1 | length 528.1
  Top Layer w20: R39.1@2152.66,626.98 2152.02,626.34 2152.02,563.11 2203.32,511.81 2375.71,511.81 2510.13,377.39 J4.3@2539.06,377.39
NetJ5_1: J5.1 R41.1 | length 254.1
  Top Layer w20: R41.1@2840.32,634.83 2843.06,632.09 J5.1@2843.06,381.89
NetJ5_3: J5.3 R45.1 | length 271.7
  Top Layer w20: J5.3@3243.06,381.89 3252.6,391.43 R45.1@3252.6,637.38 R45.1@3243.9,628.68
NetJ6_1: J6.1 R47.1 | length 994.6
  Top Layer w20: J6.1@3502.74,381.89 3638.56,246.06 3955.99,246.06 4013.15,303.23 4013.15,448.01 3859.78,601.38 R47.1@3859.78,643.92
NetJ6_3: J6.3 R51.1 | length 565.9
  Top Layer w20: R51.1@3493.96,648.68 3493.96,569.19 3540.3,522.85 3761.77,522.85 J6.3@3902.74,381.89
NetJ15_1: J15.1 R56.1 | length 263.2
  Top Layer w20: R56.1@4166.28,643.92 4169.05,641.16 J15.1@4169.05,381.89
NetJ15_3: J15.3 R64.1 | length 262
  Top Layer w20: J15.3@4569.05,381.89 R64.1@4569.05,643.92
NetR1_2: R1.2 R2.2 | length 83
  Top Layer w20: R1.2@1377.95,3170.66 R2.2@1460.95,3170.66
NetR2_1: R2.1 R3.2 | length 77.5
  Top Layer w20: R2.1@1523.94,3170.66 1600.26,3170.66 R3.2@1601.1,3169.82
NetR3_1: R3.1 R4.1 | length 78.8
  Top Layer w20: R3.1@1601.1,3106.83 1679.31,3106.83 R4.1@1679.76,3106.38
NetR4_2: R4.2 R5.1 R7.2 | length 155.8
  Top Layer w20: R4.2@1679.76,3169.38 R7.2@1760.07,3169.38 ; R7.2@1760.64,3169.95 1834.02,3169.95 R5.1@1835.48,3171.41
NetR10_2: R10.2 R11.2 | length 83.5
  Top Layer w20: R10.2@1377.42,2284.06 R11.2@1460.95,2284.06
NetR11_1: R11.1 R12.2 | length 82.5
  Top Layer w20: R11.1@1523.94,2284.06 1601.29,2284.06 R12.2@1604.95,2280.39
NetR12_1: R12.1 R13.1 | length 83.5
  Top Layer w20: R12.1@1604.95,2217.4 R13.1@1688.42,2217.4
NetR13_2: R13.2 R14.1 R17.2 | length 477.3
  Top Layer w20: R14.1@1684.11,2060.85 1692.81,2069.55 1692.81,2098.69 1708.5,2114.37 1790.19,2114.37 1815.66,2114.37 1835.11,2133.83 1835.11,2256.1 1810.82,2280.39 R17.2@1767.32,2280.39 R13.2@1688.42,2280.39
NetR24_2: R24.2 R25.2 | length 73.4
  Top Layer w20: R24.2@1384.52,1286 1454.09,1286 R25.2@1456.83,1283.26
NetR25_1: R25.1 R26.2 | length 70.4
  Top Layer w20: R25.1@1519.82,1283.26 1588.8,1283.26 R26.2@1589.83,1282.23
NetR26_1: R26.1 R27.1 | length 72.8
  Top Layer w20: R26.1@1589.83,1219.24 1661.27,1219.24 R27.1@1662.2,1220.17
NetR27_2: R27.2 R28.1 R32.2 | length 156.7
  Top Layer w20: R27.2@1673.07,1272.29 R27.2@1662.2,1283.16 1731.58,1283.16 R28.1@1732.79,1284.38 ; R32.2@1732.79,1216.8 R28.1@1732.79,1284.38 ; R28.1@1734.94,1285.54 R28.1@1733.95,1285.54 R28.1@1732.79,1284.38
NetR35_2: R35.2 R36.1 R37.2 | length 170
  Top Layer w20: R36.1@2453.21,764.43 2451.59,762.82 R37.2@2451.59,692.35 2545.39,692.35 R35.2@2547.8,694.76
NetR38_1: R38.1 R39.2 R40.1 | length 160.5
  Top Layer w20: R39.2@2152.66,689.97 2236.42,689.97 R38.1@2237.64,691.19 2233.37,695.45 R40.1@2233.37,764.43
NetR41_2: R41.2 R42.1 R43.2 | length 142.2
  Top Layer w20: R41.2@2840.32,697.83 2904.01,697.83 R43.2@2910.14,703.96 2910.14,770.89 R42.1@2912.23,772.98
NetR44_1: R44.1 R45.2 R46.1 | length 141.4
  Top Layer w20: R46.1@3186.49,773.4 3183.12,770.02 R44.1@3183.12,704.69 3248.29,704.69 R45.2@3252.6,700.37
NetR47_2: R47.2 R48.1 R49.2 | length 157.1
  Top Layer w20: R48.1@3783.4,786.43 3783.4,718.29 R49.2@3779.45,714.34 3852.36,714.34 R47.2@3859.78,706.91
NetR50_1: R50.1 R51.2 R52.1 | length 155.1
  Top Layer w20: R51.2@3493.96,711.67 3494.04,711.59 R50.1@3569.83,711.59 3569.83,779.67 R52.1@3561.94,787.56
NetR56_2: R56.2 R112.1 | length 69.6
  Top Layer w20: R56.2@4228.94,637.49 4228.94,706.58 R112.1@4229.28,706.91
NetR57_2: R57.2 R112.2 R113.1 | length 151.9
  Top Layer w10: R112.2@4160.07,700.7 R112.2@4166.28,706.91
  Top Layer w20: R57.2@4087.79,700.7 R112.2@4160.07,700.7 ; R112.2@4166.28,706.91 4166.28,777.28 R113.1@4166.64,777.63
NetR60_2: R60.2 U3.1 | length 119
  Top Layer w10: R60.2@925.2,4350.39 R60.2@925.2,4354.33 925.2,4431.75 944.88,4451.43 U3.1@944.88,4458.66 ; U3.1@946.85,4458.66 U3.1@946.85,4461.27
NetR63_1: R63.1 R114.2 R115.1 | length 152.1
  Top Layer w20: R115.1@4568.05,780.64 4567.63,780.23 4567.63,707.57 R114.2@4567.22,707.16 4640.65,707.16 R63.1@4644.07,703.74
NetR64_2: R64.2 R114.1 | length 71
  Top Layer w20: R64.2@4504.23,636.12 R114.1@4504.23,707.16
NetR101_2: R101.2 U4.3 | length 313.8
  Top Layer w10: U4.3@4202.49,5670.7 4202.49,5725.01 4189.52,5737.98 4139.42,5788.07 4139.42,5831.01 4169.52,5861.11 4252.19,5861.11 R101.2@4253.71,5862.63
NetR102_2: R102.2 U6.10 | length 73.2
  Top Layer w10: U6.10@4611.86,5820.73 4611.86,5841.71 4631.25,5861.11 R102.2@4631.25,5885.87
NetS1_3: S1.3 U3.4 | length 302.9
  Top Layer w10: S1.3@757.87,4517.72 1000,4517.72 1021.65,4539.37 U3.4@1021.65,4569.54
nRST: C24.1 JP1.2 R55.1 U2.38 | length 2626.9
  Top Layer w10: C24.1@1372.05,4461.02 R55.1@1415.24,4461.02 ; R55.1@1422.05,4461.02 1422.05,4374.8 1338.58,4291.34 JP1.2@1338.58,4173.23 1387.8,4124.02 v2(2618.11,4124.02) ; U2.38@2831.79,4582.46 U2.38@2844.49,4582.46 ; U2.38@2844.49,4583.36 2845.39,4582.46 2927.39,4582.46 3041.34,4468.5 v2(3041.34,4448.82)
  Bottom Layer w10: v2(2618.11,4124.02) 2814.96,4124.02 2903.54,4212.6 2903.54,4429.13 2923.23,4448.82 v2(3041.34,4448.82)
nRST_debug: J9.10 JP1.3 | length 412.5
  Top Layer w20: JP1.3@1438.58,4173.23 1614.17,4173.23 1643.7,4173.23 1754.72,4284.25 J9.10@1754.72,4327.56 ; J9.10@1754.72,4330.71 J9.10@1761.81,4330.71
nRST_hardware: JP1.1 R60.1 | length 383.8
  Top Layer w10: R60.1@925.2,4307.09 925.2,4281.5 1033.46,4173.23 JP1.1@1238.58,4173.23
P4.0: U10.12
P8.2: U10.14
PA0: U2.33 | length 267
  Top Layer w10: U2.33@2831.79,4484.03 2832.65,4484.89 2868.16,4484.89 2874.02,4479.03 2874.02,4370.08 2923.23,4320.87 2952.76,4320.87 v2(2962.6,4311.02)
PA1: U2.34 | length 350.9
  Top Layer w10: U2.34@2831.79,4503.72 2877.87,4503.72 2903.54,4478.04 2903.54,4379.92 2933.07,4350.39 2982.28,4350.39 3031.5,4301.18 v2(3031.5,4291.34)
PA2: U2.42
PA3: U2.43
PA4: U2.44
PA7: U2.49 | length 222.3
  Top Layer w10: U2.49@2755.02,4856.08 2755.02,4910.53 2775.59,4931.1 2897.05,4931.1 2902.3,4925.85 2904.79,4925.85 v2@2910.04,4931.1
  other v2: 2913.39,4921.26
PA14: J17.6 U2.7 | length 466.6
  Top Layer w10: J17.6@1958.66,4753.94 1963.35,4758.62 1993.35,4758.62 2090.77,4661.2 U2.7@2382.97,4661.2
PA15: J17.5 U2.8 | length 452.8
  Top Layer w10: J17.5@1948.82,4704.72 1953.35,4709.25 J17.5@1958.66,4709.25 2003.35,4709.25 2070.18,4642.42 U2.8@2372.05,4642.42
PA16: J17.4 U2.9 | length 442.3
  Top Layer w10: J17.4@1958.66,4665.35 1964.76,4659.25 2013.98,4659.25 2051.4,4621.83 U2.9@2382.97,4621.83
PA17: J17.3 U2.10 | length 405.6
  Top Layer w10: J17.3@1958.66,4609.25 1964.28,4603.63 1977.71,4603.63 1979.21,4602.14 U2.10@2361.3,4602.14
PA18_BSL_INVOKE: J17.2 JP2.2 U2.11 | length 937.4
  Top Layer w8: JP2.2@1683.07,4872.05 1751.97,4872.05 1811.02,4812.99 1811.02,4635.83 1889.76,4557.09 J17.2@1952.34,4557.09
  Top Layer w10: J17.2@1958.66,4559.25 2010.04,4559.25 2033.24,4582.46 U2.11@2382.97,4582.46
PA21: J17.1 U2.17 | length 646.3
  Top Layer w10: v2(2263.78,4360.24) 2288.22,4384.68 2458.84,4384.68 2459.75,4385.59 U2.17@2459.75,4407.26
  Bottom Layer w10: J17.1@1958.66,4507.87 2204.72,4507.87 2263.78,4448.82 v2(2263.78,4360.24)
PA25: U2.26
PB0: U2.47 | length 198.4
  Top Layer w10: U2.47@2831.79,4759.62 2832.7,4760.53 2870.76,4760.53 2879.72,4769.48 2879.72,4863 2865.42,4877.3 2839.24,4877.3 v2(2834.65,4881.89)
PB1: U2.48 | length 48.8
  Top Layer w10: U2.48@2831.79,4779.31 2831.79,4810.14 v2(2844.49,4822.83)
PB4: U2.52 | length 138.5
  Top Layer w10: U2.52@2695.97,4856.08 2695.97,4972.94 2706.69,4983.66 v2(2706.69,4990.16)
PB5: U2.53 | length 176.8
  Top Layer w10: U2.53@2676.28,4856.08 2676.28,5010.16 2687.01,5020.89 2687.01,5027.96 v2(2686.69,5028.27)
PB10: U2.62
PB13: U2.1
PB14: U2.2
PB17: J18.6 U2.14 | length 267.6
  Top Layer w10: J18.6@2153.94,4430.71 2153.94,4431.03 2164.01,4441.1 2164.33,4441.1 2246.63,4523.4 U2.14@2382.97,4523.4
PB18: J18.5 U2.15 | length 277.7
  Top Layer w10: J18.5@2145.67,4380.71 2153.62,4380.71 2162.83,4389.92 2165.51,4389.92 2280.21,4504.62 U2.15@2372.05,4504.62
PB19: J18.4 U2.16 | length 304.6
  Top Layer w10: J18.4@2145.67,4322.3 2145.67,4322.76 2163.94,4341.03 2164.4,4341.03 2307.03,4483.66 2382.61,4483.66 U2.16@2382.97,4484.03
PB20: J18.1 U2.21 | length 558.2
  Top Layer w10: J18.1@2135.83,4183.07 2421.26,4183.07 2538.49,4300.3 U2.21@2538.49,4407.26
PB21: J18.2 U2.20 | length 506.6
  Top Layer w10: J18.2@2145.67,4222.44 2153.94,4230.71 2439.37,4230.71 2518.8,4310.14 U2.20@2518.8,4407.26
PB22: J18.3 U2.19 | length 447.6
  Top Layer w10: J18.3@2155.51,4281.5 2155.51,4278.81 2159.24,4275.09 2161.92,4275.09 2175.2,4261.81 2440.94,4261.81 2499.12,4319.98 2499.12,4388.88 U2.19@2500,4389.76
PB23: U2.22
PB24: U2.23
PB25: U2.27
R13: C54.2 U10.1 | length 236.1
  Top Layer w8: C54.2@4055.12,3720.47 4187.99,3720.47 4247.05,3661.42 U10.1@4266.73,3661.42
R23: C53.2 U10.2 | length 216.3
  Top Layer w10: C53.2@4055.12,3651.57 C53.2@4059.05,3651.57 ; C53.2@4059.05,3653.07 4161.89,3653.07 4173.23,3641.73 U10.2@4266.73,3641.73
R33: C52.2 U10.3 | length 214
  Top Layer w10: C52.2@4064.96,3592.52 4124.02,3592.52 4153.54,3622.05 U10.3@4266.73,3622.05
REACT: D2.2 J8.1 J13.5 pad.2@2802.04,6187.02 U2.39 U8.3 | length 4667.4
  Top Layer w10: D2.2@1351.46,6097.16 J8.1@1351.46,6429.86 1584.99,6663.39 2088.37,6663.39 2196.87,6554.88 2196.87,6488.13 2242.23,6442.77 J13.5@2242.23,6438.92 ; v1(2568.9,6213.18) U8.3@2940.24,6213.18 ; U2.39@2831.79,4602.14 2951.85,4602.14 3105.17,4448.82 v1(3110.24,4448.82)
  Bottom Layer w10: J13.5@2234.25,6427.17 2253.98,6427.17 2319.72,6361.42 2421.33,6361.42 2568.9,6213.85 v1(2568.9,6213.18) 2573.49,6208.59 2573.49,6186.35 2913.39,5846.46 2913.39,5295.28 3208.66,5000 3208.66,4537.4 3127.78,4456.52 3124.44,4456.52 3116.73,4448.82 v1(3110.24,4448.82)
REACT_ISO: J14.3 U8.6 | length 323.6
  Top Layer w10: U8.6@3152.84,6213.18 3333.58,6213.18 3358.58,6188.18 J14.3@3466.1,6188.18
RS232_PORT_DTR: D3.2 pad.1@4251.97,6348.43 RS1.4 | length 1060.9
  Top Layer w10: D3.2@4239.31,6278.28 4239.31,6325.91 4273.62,6360.21 v1(4329.49,6360.21)
  Bottom Layer w10: v1(4329.49,6360.21) v1@4331.07,6358.63 ; v1@4330.71,6358.27 4332.65,6360.21 5100.15,6360.21 RS1.4@5196.63,6456.69
RS232_PORT_RTS: D4.2 pad.2@4527.56,6289.37 RS1.7 | length 989
  Top Layer w10: D4.2@4303.9,6278.18 4303.9,6303.43 4317.73,6317.27 4655.51,6317.27 ; 4655.51,6318.9 4783.46,6446.85 4783.46,6515.75 4901.57,6633.86 5019.69,6633.86 5034.63,6618.92 RS1.7@5034.63,6568.69
RS485_A: C38.1 J12.1 R103.1 R107.2 U7.6 | length 475.3
  Top Layer w10: R103.1@5347.55,5000.68 5416.68,5000.68 C38.1@5422.68,5006.69 ; R107.2@5424.64,4940.64 5424.64,5017.41 5422.68,5019.36 5422.68,5032.04 5449.99,5059.34 U7.6@5449.99,5098.43
  Top Layer w15: R107.2@5424.64,4940.64 5424.64,4856.93 5406.61,4838.9 J12.1@5406.61,4753.94 J12.1@5430.37,4777.7
RS485_B: C38.2 J12.2 R107.1 R108.2 U7.7 | length 603.7
  Top Layer w10: R108.2@5324.56,5171.47 5329.65,5166.38 5334.74,5171.47 5464.89,5171.47 5499.99,5136.37 U7.7@5499.99,5098.43 5495.46,5093.9 5495.46,5054.82 5485.68,5045.03 C38.2@5485.68,5006.69 5487.63,5004.74 R107.1@5487.63,4940.64
  Top Layer w15: R107.1@5487.63,4940.64 5487.63,4857.78 5506.61,4838.8 J12.2@5506.61,4753.94 J12.2@5497.78,4762.76
RST/SBWTDIO: C58.1 J16.3 R65.1 U10.10 | length 1343
  Top Layer w10: R65.1@3179.13,2931.95 3179.13,2952.76 3202.7,2976.32 J16.3@3297.24,2976.32 3458.61,2976.32 3809.06,3326.77 4025.59,3326.77 4058.89,3360.08 4058.89,3384.81 4059.92,3385.83 4104.33,3385.83 4202.76,3484.25 U10.10@4266.73,3484.25
RTS_FTDI: J10.6 U2.36 | length 2078.2
  Top Layer w10: U2.36@2831.79,4543.09 2832.7,4542.18 2898.77,4542.18 2982.28,4458.66 2982.28,4412.33 3044.22,4350.39 3152.95,4350.39 3162.8,4360.24 v1(3169.29,4360.24)
  Bottom Layer w10: v1(3169.29,4360.24) 3277.56,4360.24 3307.09,4389.76 3307.09,5458.94 3591.88,5743.73 J10.6@3591.88,5751.41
